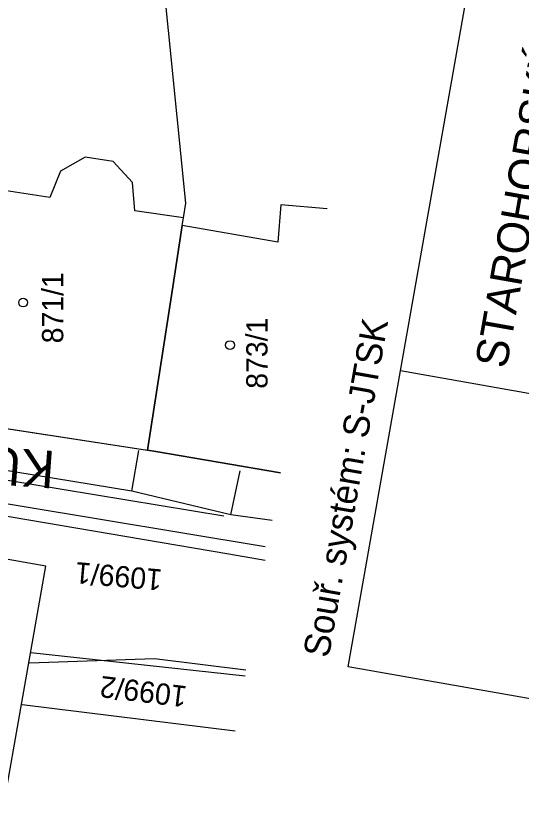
# Model space of a CAD drawing. Extents: x -534481 to -534256, y -1190577 to -1190138.
# Drawn here: x -534326.68 to -534306.48, y -1190249.56 to -1190218.06 of the extents above; entities that cross this region are included whole.
import ezdxf

# ---------------------------------------------------------------- set-up
doc = ezdxf.new("R2010")
doc.units = 0
for name, color, linetype in [('07_KANALIZACE', 7, 'Continuous'), ('14', 7, 'Continuous'), ('_N_text', 7, 'Continuous'), ('_rozpiska', 7, 'Continuous'), ('_tenka', 7, 'Continuous'), ('Hranice parcel', 7, 'Continuous'), ('Level 30', 7, 'Continuous'), ('Parcelní čísla', 7, 'Continuous'), ('Polygon budovy', 7, 'Continuous'), ('Vrstva 1', 7, 'Continuous'), ('Značky budov', 7, 'Continuous')]:
    doc.layers.add(name, color=color, linetype=linetype)

msp = doc.modelspace()

# ---------------------------------------------------------------- linework, layer by layer
at = {"layer": '07_KANALIZACE'}
msp.add_line((-534326.086, -1190243.533), (-534317.518, -1190244.467), dxfattribs=at)
at = {"layer": '14'}
for points in [[(-534316.429, -1190238.25), (-534318.08, -1190238.03), (-534322.04, -1190237.08), (-534332.22, -1190235.41), (-534338.777, -1190234.334), (-534339.342, -1190238.274), (-534345.981, -1190237.953), (-534362.202, -1190237.552), (-534365.29, -1190237.5)], [(-534322.04, -1190237.08), (-534321.76, -1190235.45)], [(-534318.08, -1190238.03), (-534317.71, -1190236.27)]]:
    msp.add_lwpolyline(points, dxfattribs=at)
at = {"layer": '_N_text'}
msp.add_lwpolyline([(-534329.865, -1190239.303), (-534335.236, -1190269.762), (-534330.848, -1190270.536), (-534325.477, -1190240.077)], close=True, dxfattribs=at)
at = {"layer": '_rozpiska'}
for p, q in [((-534313.394, -1190244.109), (-534298.633, -1190160.401)), ((-534278.064, -1190238.127), (-534311.305, -1190232.266)), ((-534280.153, -1190249.971), (-534313.394, -1190244.109))]:
    msp.add_line(p, q, dxfattribs=at)
at = {"layer": '_tenka'}
msp.add_lwpolyline([(-534366.521, -1190234.728), (-534348.981, -1190235.231), (-534336.32, -1190236.042), (-534316.711, -1190239.297)], dxfattribs=at)
at = {"layer": 'Hranice parcel'}
for p, q in [((-534332.08, -1190233.8), (-534321.41, -1190235.44)), ((-534326.423, -1190245.612), (-534317.914, -1190246.672))]:
    msp.add_line(p, q, dxfattribs=at)
for points in [[(-534321.41, -1190235.44), (-534320.43, -1190229.08), (-534320.03, -1190226.45), (-534319.98, -1190226.15), (-534319.89, -1190225.56), (-534320.92, -1190215.18)], [(-534316.094, -1190236.35), (-534321.08, -1190235.49), (-534321.41, -1190235.44)], [(-534326.128, -1190243.941), (-534321.13, -1190243.77), (-534317.482, -1190244.222)]]:
    msp.add_lwpolyline(points, dxfattribs=at)
at = {"layer": 'Level 30'}
for p in [(-534331.85, -1190235.84), (-534318.36, -1190238.06), (-534318.36, -1190238.06)]:
    msp.add_line(p, (-534318.36, -1190238.06), dxfattribs=at)
at = {"layer": 'Polygon budovy'}
msp.add_lwpolyline([(-534330.71, -1190224.5), (-534330.89, -1190225.71), (-534332.08, -1190233.8), (-534321.41, -1190235.44), (-534320.43, -1190229.08), (-534320.03, -1190226.45), (-534319.98, -1190226.15), (-534321.92, -1190225.86), (-534322.01, -1190224.729), (-534322.782, -1190223.898), (-534323.902, -1190223.723), (-534324.89, -1190224.281), (-534325.32, -1190225.33)], close=True, dxfattribs=at)
msp.add_lwpolyline([(-534314.231, -1190225.785), (-534316.08, -1190225.63), (-534316.21, -1190227.12), (-534320.03, -1190226.45), (-534320.43, -1190229.08), (-534321.41, -1190235.44), (-534321.08, -1190235.49), (-534316.094, -1190236.35)], dxfattribs=at)
at = {"layer": 'Vrstva 1'}
for points in [[(-534316.712, -1190239.853), (-534318.166, -1190239.603), (-534321.619, -1190239.01), (-534330.798, -1190237.457)], [(-534316.712, -1190239.853), (-534318.166, -1190239.603)]]:
    msp.add_lwpolyline(points, dxfattribs=at)
at = {"layer": 'Značky budov'}
for centre in [(-534326.391, -1190229.536), (-534318.117, -1190231.234)]:
    msp.add_circle(centre, 0.175, dxfattribs=at)

# ---------------------------------------------------------------- texts
at = {"layer": '_N_text'}
msp.add_text('KÚ, SO-01', height=1.5, rotation=175.8322, dxfattribs=at).set_placement((-534325.077, -1190235.481))
at = {"layer": '_rozpiska'}
for s, height, p in [('STAROHORSKÝ POTOK, HLUK - ŘKM 0,000 ', 1.2825, (-534307.068, -1190232.21)), ('Souř. systém: S-JTSK', 1.04194, (-534314.172, -1190243.775))]:
    msp.add_text(s, height=height, rotation=80, dxfattribs=at).set_placement(p)
at = {"layer": 'Parcelní čísla'}
for s, rotation, p in [('871/1', 90, (-534324.784, -1190231.164)), ('873/1', 90, (-534316.619, -1190232.982)), ('1099/1', 175, (-534320.803, -1190240.214)), ('1099/2', 173, (-534319.805, -1190244.888))]:
    msp.add_text(s, height=0.85, rotation=rotation, dxfattribs=at).set_placement(p)

doc.saveas('drawing.dxf')
